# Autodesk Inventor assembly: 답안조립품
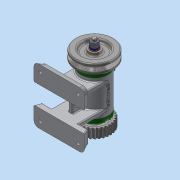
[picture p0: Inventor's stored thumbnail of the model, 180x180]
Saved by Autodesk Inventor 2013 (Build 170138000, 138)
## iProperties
Created: 2016-07
Part Number: 답안조립품
Document SubType Name: Assembly
Designer: Administrator
Author: Administrator
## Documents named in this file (16)
- C:\Users\Administrator\Desktop\460708V1026\답안조립품.iam
- C:\Users\Administrator\Desktop\460708V1026\본체.ipt
- C:\Users\Administrator\Desktop\460708V1026\V벨트풀리.ipt
- C:\Users\Administrator\Desktop\460708V1026\너트 M 8.ipt
- C:\Users\Administrator\Desktop\460708V1026\니플 M 6 x 0.75.ipt
- C:\Users\Administrator\Desktop\460708V1026\베어링 15 x 32 x 9.ipt
- C:\Users\Administrator\Desktop\460708V1026\볼트 M 6 x 8.ipt
- C:\Users\Administrator\Desktop\460708V1026\볼트 M4 x 12.ipt
- C:\Users\Administrator\Desktop\460708V1026\스퍼기어.ipt
- C:\Users\Administrator\Desktop\460708V1026\스프링와셔 8.ipt
- C:\Users\Administrator\Desktop\460708V1026\오일 실 15 25 7.ipt
- C:\Users\Administrator\Desktop\460708V1026\와셔 6x11.5.ipt
- C:\Users\Administrator\Desktop\460708V1026\와셔 8x17.ipt
- C:\Users\Administrator\Desktop\460708V1026\축.ipt
- C:\Users\Administrator\Desktop\460708V1026\커버.ipt
- C:\Users\Administrator\Desktop\460708V1026\키 3 x 3 x 12.ipt
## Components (11 placed, 3 different names)
1. V벨트풀리:1
2. KS B 2023 6002 - 15 x 32 x 9:1
3. KS B 2023 6002 - 15 x 32 x 9:2
4. ISO 4762 M4 x 12:2
5. ISO 4762 M4 x 12:3
6. ISO 4762 M4 x 12:4
7. ISO 4762 M4 x 12:5
8. ISO 4762 M4 x 12:1
9. ISO 4762 M4 x 12:6
10. ISO 4762 M4 x 12:7
11. ISO 4762 M4 x 12:8
